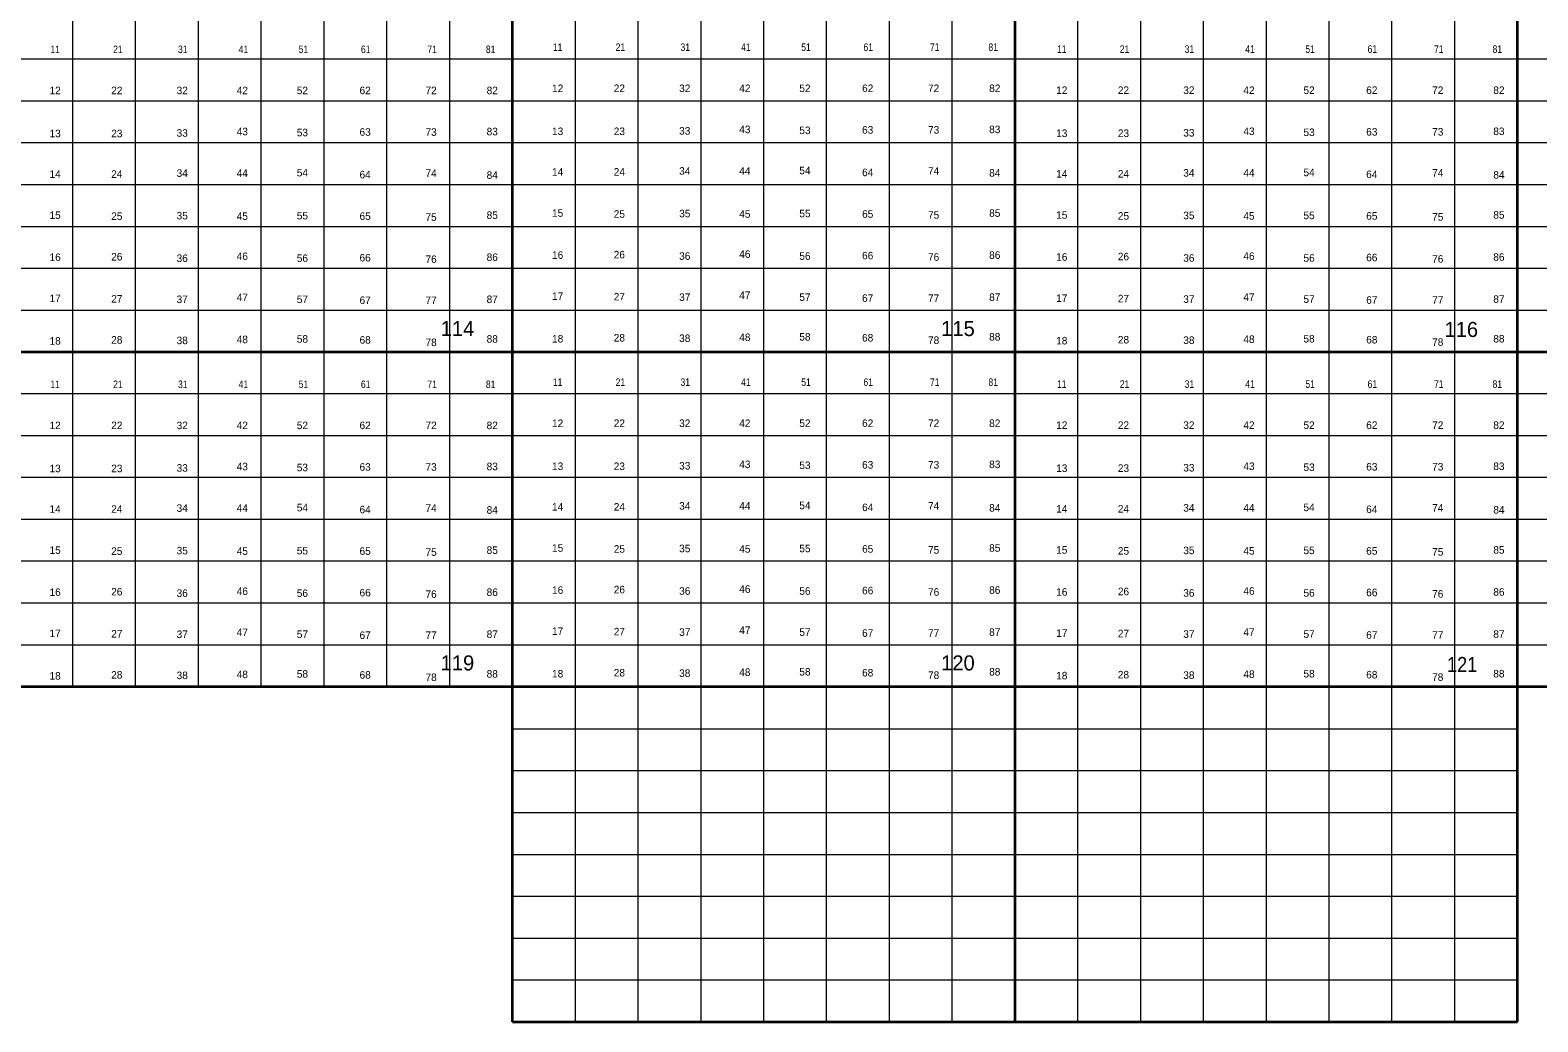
# Model space of a CAD drawing. Extents: x 639000 to 672000, y 222000 to 252000.
# Drawn here: x 651120 to 660121, y 222000 to 227921 of the extents above; entities that cross this region are included whole.
import ezdxf
from ezdxf.enums import TextEntityAlignment as Align

# ---------------------------------------------------------------- set-up
doc = ezdxf.new("R2010")
doc.units = 0
doc.header["$LTSCALE"] = 18
doc.header["$PDMODE"] = 32
doc.header["$PDSIZE"] = 9
doc.layers.add('1', color=7, linetype='Continuous', lineweight=13)
doc.layers.add('2', color=7, linetype='Continuous')
doc.layers.add('29', color=7, linetype='Continuous')

msp = doc.modelspace()

# ---------------------------------------------------------------- linework, layer by layer
at = {"layer": '1'}
for p, q in [((651375, 224000), (651375, 252000)), ((651750, 224000), (651750, 252000)), ((652125, 224000), (652125, 252000)), ((652500, 224000), (652500, 252000)), ((652875, 224000), (652875, 252000)), ((653250, 224000), (653250, 252000)), ((653625, 224000), (653625, 252000)), ((654375, 222000), (654375, 252000)), ((654750, 222000), (654750, 252000)), ((655125, 222000), (655125, 252000)), ((655500, 222000), (655500, 252000)), ((655875, 222000), (655875, 252000)), ((656250, 222000), (656250, 252000)), ((656625, 222000), (656625, 252000)), ((657375, 222000), (657375, 248000)), ((657750, 222000), (657750, 248000)), ((658125, 222000), (658125, 248000)), ((658500, 222000), (658500, 248000)), ((658875, 222000), (658875, 248000)), ((659250, 222000), (659250, 248000)), ((659625, 222000), (659625, 248000)), ((642000, 227750), (663000, 227750)), ((642000, 227500), (663000, 227500)), ((642000, 227250), (663000, 227250)), ((642000, 227000), (663000, 227000)), ((642000, 226750), (663000, 226750)), ((642000, 226500), (663000, 226500)), ((642000, 226250), (663000, 226250)), ((663000, 225750), (642000, 225750)), ((663000, 225500), (642000, 225500)), ((663000, 225250), (642000, 225250)), ((663000, 225000), (642000, 225000)), ((663000, 224750), (642000, 224750)), ((663000, 224500), (642000, 224500)), ((663000, 224250), (642000, 224250)), ((654000, 223750), (660000, 223750)), ((654000, 223500), (660000, 223500)), ((654000, 223250), (660000, 223250)), ((654000, 223000), (660000, 223000)), ((654000, 222750), (660000, 222750)), ((654000, 222500), (660000, 222500)), ((654000, 222250), (660000, 222250))]:
    msp.add_line(p, q, dxfattribs=at)
at = {"layer": '1', "lineweight": 35}
for p, q in [((654000, 222000), (654000, 252000)), ((657000, 222000), (657000, 252000)), ((660000, 222000), (660000, 248000)), ((642000, 226000), (663000, 226000)), ((663000, 224000), (642000, 224000)), ((654000, 222000), (660000, 222000))]:
    msp.add_line(p, q, dxfattribs=at)
at = {"layer": '1'}
for p in [(654000, 224000), (657000, 224000), (660000, 224000)]:
    msp.add_point(p, dxfattribs=at)

# ---------------------------------------------------------------- texts
at = {"layer": '2'}
for s, p in [('114', (653671.21, 226094.85)), ('115', (656658.96, 226094.85)), ('119', (653670.74, 224098.13)), ('120', (656658.79, 224098.13))]:
    msp.add_text(s, height=90, rotation=359.94, dxfattribs=at).set_placement(p, align=Align.CENTER)
msp.add_text('116', height=90, dxfattribs=at).set_placement((659663.59, 226089.35), align=Align.CENTER)
at = {"layer": '2', "width": 0.9}
msp.add_text('121', height=90, dxfattribs=at).set_placement((659668.72, 224088.51), align=Align.CENTER)
at = {"layer": '29', "width": 0.85}
for s, p in [('11', (651269.26, 227784.35)), ('21', (651643.86, 227784.35)), ('31', (652031.16, 227784.35)), ('41', (652393.07, 227784.35)), ('51', (652751.8, 227784.35)), ('61', (653123.23, 227784.35)), ('71', (653520.05, 227784.35)), ('81', (653869.26, 227784.35)), ('11', (654269.27, 227797.21)), ('21', (654643.88, 227797.21)), ('31', (655031.18, 227797.21)), ('41', (655393.08, 227797.21)), ('51', (655751.81, 227797.21)), ('61', (656123.24, 227797.21)), ('71', (656520.07, 227797.21)), ('81', (656869.28, 227797.21)), ('11', (657278.8, 227785.66)), ('21', (657653.4, 227785.66)), ('31', (658040.7, 227785.66)), ('41', (658402.61, 227785.66)), ('51', (658761.34, 227785.66)), ('61', (659132.77, 227785.66)), ('71', (659529.6, 227785.66)), ('81', (659878.8, 227785.66)), ('11', (651269.26, 225784.35)), ('21', (651643.86, 225784.35)), ('31', (652031.16, 225784.35)), ('41', (652393.07, 225784.35)), ('51', (652751.8, 225784.35)), ('61', (653123.23, 225784.35)), ('71', (653520.05, 225784.35)), ('81', (653869.26, 225784.35)), ('11', (654269.27, 225797.21)), ('21', (654643.88, 225797.21)), ('31', (655031.18, 225797.21)), ('41', (655393.08, 225797.21)), ('51', (655751.81, 225797.21)), ('61', (656123.24, 225797.21)), ('71', (656520.07, 225797.21)), ('81', (656869.28, 225797.21)), ('11', (657278.8, 225785.66)), ('21', (657653.4, 225785.66)), ('31', (658040.7, 225785.66)), ('41', (658402.61, 225785.66)), ('51', (658761.34, 225785.66)), ('61', (659132.77, 225785.66)), ('71', (659529.6, 225785.66)), ('81', (659878.8, 225785.66))]:
    msp.add_text(s, height=45, dxfattribs=at).set_placement(p, align=Align.CENTER)
at = {"layer": '29'}
for s, p in [('12', (651269.25, 227538.96)), ('22', (651637.51, 227538.96)), ('32', (652027.99, 227538.96)), ('42', (652386.72, 227538.96)), ('52', (652745.45, 227538.96)), ('62', (653120.05, 227538.96)), ('72', (653513.7, 227538.96)), ('82', (653878.78, 227538.96)), ('12', (654269.27, 227551.82)), ('22', (654637.53, 227551.82)), ('32', (655028, 227551.82)), ('42', (655386.73, 227551.82)), ('52', (655745.46, 227551.82)), ('62', (656120.07, 227551.82)), ('72', (656513.72, 227551.82)), ('82', (656878.8, 227551.82)), ('12', (657278.8, 227540.27)), ('22', (657647.05, 227540.27)), ('32', (658037.53, 227540.27)), ('42', (658396.26, 227540.27)), ('52', (658754.99, 227540.27)), ('62', (659129.59, 227540.27)), ('72', (659523.24, 227540.27)), ('82', (659888.32, 227540.27)), ('13', (651269.26, 227282.02)), ('23', (651637.51, 227282.02)), ('33', (652027.99, 227284.91)), ('43', (652386.72, 227293.57)), ('53', (652745.45, 227287.8)), ('63', (653120.05, 227290.68)), ('73', (653513.7, 227290.68)), ('83', (653878.78, 227293.57)), ('13', (654269.27, 227294.88)), ('23', (654637.53, 227294.88)), ('33', (655028, 227297.77)), ('43', (655386.73, 227306.43)), ('53', (655745.46, 227300.65)), ('63', (656120.07, 227303.54)), ('73', (656513.72, 227303.54)), ('83', (656878.8, 227306.43)), ('13', (657278.8, 227283.33)), ('23', (657647.05, 227283.33)), ('33', (658037.53, 227286.22)), ('43', (658396.26, 227294.88)), ('53', (658754.99, 227289.11)), ('63', (659129.59, 227291.99)), ('73', (659523.24, 227291.99)), ('83', (659888.33, 227294.88)), ('24', (651637.51, 227039.52)), ('34', (652027.99, 227045.29)), ('44', (652386.72, 227045.29)), ('54', (652745.45, 227048.18)), ('74', (653513.7, 227045.29)), ('14', (654269.27, 227052.38)), ('24', (654637.53, 227052.38)), ('34', (655028, 227058.15)), ('44', (655386.73, 227058.15)), ('54', (655745.46, 227061.04)), ('64', (656120.07, 227049.49)), ('74', (656513.72, 227058.15)), ('84', (656878.8, 227046.6)), ('14', (657278.8, 227040.83)), ('24', (657647.05, 227040.83)), ('34', (658037.53, 227046.6)), ('44', (658396.26, 227046.6)), ('54', (658754.99, 227049.49)), ('74', (659523.24, 227046.6)), ('14', (651269.26, 227039.52)), ('64', (653120.05, 227036.63)), ('84', (653878.78, 227033.74)), ('64', (659129.59, 227037.94)), ('84', (659888.33, 227035.05)), ('15', (651269.26, 226794.13)), ('25', (651637.51, 226788.35)), ('35', (652027.99, 226791.24)), ('45', (652386.72, 226788.35)), ('55', (652745.45, 226791.24)), ('65', (653120.05, 226788.36)), ('75', (653513.7, 226782.58)), ('85', (653878.78, 226794.13)), ('15', (654269.27, 226806.98)), ('25', (654637.53, 226801.21)), ('35', (655028, 226804.1)), ('45', (655386.73, 226801.21)), ('55', (655745.46, 226804.1)), ('65', (656120.07, 226801.21)), ('75', (656513.72, 226795.44)), ('85', (656878.8, 226806.99)), ('15', (657278.8, 226795.44)), ('25', (657647.05, 226789.66)), ('35', (658037.53, 226792.55)), ('45', (658396.26, 226789.66)), ('55', (658754.99, 226792.55)), ('65', (659129.59, 226789.66)), ('75', (659523.24, 226783.89)), ('85', (659888.33, 226795.44)), ('16', (651269.26, 226542.96)), ('26', (651637.51, 226545.85)), ('36', (652027.99, 226537.19)), ('46', (652386.72, 226548.74)), ('56', (652745.45, 226537.19)), ('66', (653120.05, 226540.08)), ('76', (653513.7, 226531.42)), ('86', (653878.78, 226542.96)), ('16', (654269.27, 226555.82)), ('26', (654637.53, 226558.71)), ('36', (655028, 226550.05)), ('46', (655386.73, 226561.59)), ('56', (655745.46, 226550.05)), ('66', (656120.07, 226552.93)), ('76', (656513.72, 226544.27)), ('86', (656878.8, 226555.82)), ('16', (657278.8, 226544.27)), ('26', (657647.05, 226547.16)), ('36', (658037.53, 226538.5)), ('46', (658396.26, 226550.05)), ('56', (658754.99, 226538.5)), ('66', (659129.59, 226541.39)), ('76', (659523.24, 226532.72)), ('86', (659888.33, 226544.27)), ('17', (651269.26, 226297.57)), ('27', (651637.51, 226294.69)), ('37', (652027.99, 226291.8)), ('47', (652386.72, 226303.35)), ('57', (652745.45, 226291.8)), ('67', (653120.05, 226286.03)), ('77', (653513.7, 226286.03)), ('87', (653878.78, 226291.8)), ('17', (654269.27, 226310.43)), ('27', (654637.53, 226307.54)), ('37', (655028, 226304.66)), ('47', (655386.73, 226316.2)), ('57', (655745.46, 226304.66)), ('67', (656120.07, 226298.88)), ('77', (656513.72, 226298.88)), ('87', (656878.8, 226304.66)), ('17', (657278.8, 226298.88)), ('27', (657647.05, 226295.99)), ('37', (658037.53, 226293.11)), ('47', (658396.26, 226304.65)), ('57', (658754.99, 226293.11)), ('67', (659129.59, 226287.33)), ('77', (659523.25, 226287.33)), ('87', (659888.33, 226293.11)), ('28', (651637.51, 226049.3)), ('48', (652386.72, 226052.18)), ('58', (652745.45, 226055.07)), ('68', (653120.05, 226049.3)), ('88', (653878.78, 226055.07)), ('18', (654269.27, 226056.38)), ('28', (654637.53, 226062.15)), ('38', (655028, 226059.27)), ('48', (655386.73, 226065.04)), ('58', (655745.46, 226067.93)), ('68', (656120.07, 226062.15)), ('88', (656878.8, 226067.93)), ('28', (657647.05, 226050.6)), ('48', (658396.26, 226053.49)), ('58', (658754.99, 226056.38)), ('68', (659129.59, 226050.6)), ('88', (659888.32, 226056.38)), ('18', (651269.25, 226043.52)), ('38', (652027.99, 226046.41)), ('78', (653513.7, 226034.86)), ('78', (656513.72, 226047.72)), ('18', (657278.8, 226044.83)), ('38', (658037.53, 226047.72)), ('78', (659523.24, 226036.17)), ('12', (651269.25, 225538.96)), ('22', (651637.51, 225538.96)), ('32', (652027.99, 225538.96)), ('42', (652386.72, 225538.96)), ('52', (652745.45, 225538.96)), ('62', (653120.05, 225538.96)), ('72', (653513.7, 225538.96)), ('82', (653878.78, 225538.96)), ('12', (654269.27, 225551.82)), ('22', (654637.53, 225551.82)), ('32', (655028, 225551.82)), ('42', (655386.73, 225551.82)), ('52', (655745.46, 225551.82)), ('62', (656120.07, 225551.82)), ('72', (656513.72, 225551.82)), ('82', (656878.8, 225551.82)), ('12', (657278.8, 225540.27)), ('22', (657647.05, 225540.27)), ('32', (658037.53, 225540.27)), ('42', (658396.26, 225540.27)), ('52', (658754.99, 225540.27)), ('62', (659129.59, 225540.27)), ('72', (659523.24, 225540.27)), ('82', (659888.32, 225540.27)), ('13', (651269.26, 225282.02)), ('23', (651637.51, 225282.02)), ('33', (652027.99, 225284.91)), ('43', (652386.72, 225293.57)), ('53', (652745.45, 225287.8)), ('63', (653120.05, 225290.68)), ('73', (653513.7, 225290.68)), ('83', (653878.78, 225293.57)), ('13', (654269.27, 225294.88)), ('23', (654637.53, 225294.88)), ('33', (655028, 225297.77)), ('43', (655386.73, 225306.43)), ('53', (655745.46, 225300.65)), ('63', (656120.07, 225303.54)), ('73', (656513.72, 225303.54)), ('83', (656878.8, 225306.43)), ('13', (657278.8, 225283.33)), ('23', (657647.05, 225283.33)), ('33', (658037.53, 225286.22)), ('43', (658396.26, 225294.88)), ('53', (658754.99, 225289.11)), ('63', (659129.59, 225291.99)), ('73', (659523.24, 225291.99)), ('83', (659888.33, 225294.88)), ('54', (655745.46, 225061.04)), ('14', (651269.26, 225039.52)), ('24', (651637.51, 225039.52)), ('34', (652027.99, 225045.29)), ('44', (652386.72, 225045.29)), ('54', (652745.45, 225048.18)), ('64', (653120.05, 225036.63)), ('74', (653513.7, 225045.29)), ('84', (653878.78, 225033.74)), ('14', (654269.27, 225052.38)), ('24', (654637.53, 225052.38)), ('34', (655028, 225058.15)), ('44', (655386.73, 225058.15)), ('64', (656120.07, 225049.49)), ('74', (656513.72, 225058.15)), ('84', (656878.8, 225046.6)), ('14', (657278.8, 225040.83)), ('24', (657647.05, 225040.83)), ('34', (658037.53, 225046.6)), ('44', (658396.26, 225046.6)), ('54', (658754.99, 225049.49)), ('64', (659129.59, 225037.94)), ('74', (659523.24, 225046.6)), ('84', (659888.33, 225035.05)), ('15', (651269.26, 224794.13)), ('35', (652027.99, 224791.24)), ('55', (652745.45, 224791.24)), ('85', (653878.78, 224794.13)), ('15', (654269.27, 224806.98)), ('25', (654637.53, 224801.21)), ('35', (655028, 224804.1)), ('45', (655386.73, 224801.21)), ('55', (655745.46, 224804.1)), ('65', (656120.07, 224801.21)), ('75', (656513.72, 224795.44)), ('85', (656878.8, 224806.99)), ('15', (657278.8, 224795.44)), ('25', (657647.05, 224789.66)), ('35', (658037.53, 224792.55)), ('45', (658396.26, 224789.66)), ('55', (658754.99, 224792.55)), ('65', (659129.59, 224789.66)), ('85', (659888.33, 224795.44)), ('25', (651637.51, 224788.35)), ('45', (652386.72, 224788.35)), ('65', (653120.05, 224788.36)), ('75', (653513.7, 224782.58)), ('75', (659523.24, 224783.89)), ('16', (651269.26, 224542.96)), ('26', (651637.51, 224545.85)), ('36', (652027.99, 224537.19)), ('46', (652386.72, 224548.74)), ('56', (652745.45, 224537.19)), ('66', (653120.05, 224540.08)), ('76', (653513.7, 224531.42)), ('86', (653878.78, 224542.96)), ('16', (654269.27, 224555.82)), ('26', (654637.53, 224558.71)), ('36', (655028, 224550.05)), ('46', (655386.73, 224561.59)), ('56', (655745.46, 224550.05)), ('66', (656120.07, 224552.93)), ('76', (656513.72, 224544.27)), ('86', (656878.8, 224555.82)), ('16', (657278.8, 224544.27)), ('26', (657647.05, 224547.16)), ('36', (658037.53, 224538.5)), ('46', (658396.26, 224550.05)), ('56', (658754.99, 224538.5)), ('66', (659129.59, 224541.39)), ('76', (659523.24, 224532.72)), ('86', (659888.33, 224544.27)), ('17', (651269.26, 224297.57)), ('27', (651637.51, 224294.69)), ('37', (652027.99, 224291.8)), ('47', (652386.72, 224303.35)), ('57', (652745.45, 224291.8)), ('67', (653120.05, 224286.03)), ('77', (653513.7, 224286.03)), ('87', (653878.78, 224291.8)), ('17', (654269.27, 224310.43)), ('27', (654637.53, 224307.54)), ('37', (655028, 224304.66)), ('47', (655386.73, 224316.2)), ('57', (655745.46, 224304.66)), ('67', (656120.07, 224298.88)), ('77', (656513.72, 224298.88)), ('87', (656878.8, 224304.66)), ('17', (657278.8, 224298.88)), ('27', (657647.05, 224295.99)), ('37', (658037.53, 224293.11)), ('47', (658396.26, 224304.65)), ('57', (658754.99, 224293.11)), ('67', (659129.59, 224287.33)), ('77', (659523.25, 224287.33)), ('87', (659888.33, 224293.11)), ('18', (651269.25, 224043.52)), ('28', (651637.51, 224049.3)), ('38', (652027.99, 224046.41)), ('48', (652386.72, 224052.18)), ('58', (652745.45, 224055.07)), ('68', (653120.05, 224049.3)), ('78', (653513.7, 224034.86)), ('88', (653878.78, 224055.07)), ('18', (654269.27, 224056.38)), ('28', (654637.53, 224062.15)), ('38', (655028, 224059.27)), ('48', (655386.73, 224065.04)), ('58', (655745.46, 224067.93)), ('68', (656120.07, 224062.15)), ('78', (656513.72, 224047.72)), ('88', (656878.8, 224067.93)), ('18', (657278.8, 224044.83)), ('28', (657647.05, 224050.6)), ('38', (658037.53, 224047.72)), ('48', (658396.26, 224053.49)), ('58', (658754.99, 224056.38)), ('68', (659129.59, 224050.6)), ('78', (659523.24, 224036.17)), ('88', (659888.32, 224056.38))]:
    msp.add_text(s, height=45, dxfattribs=at).set_placement(p, align=Align.CENTER)

doc.saveas('drawing.dxf')
